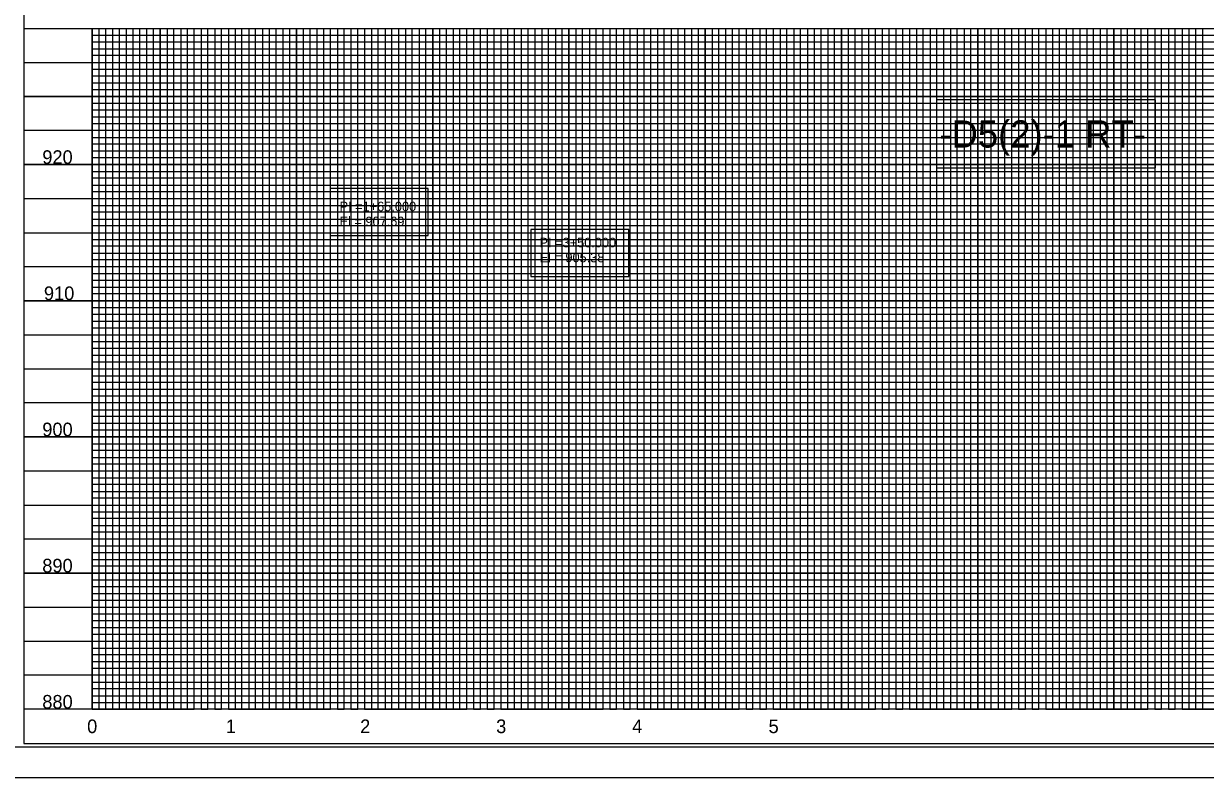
# Model space of a CAD drawing. Extents: x 1647943 to 1651624, y 802691 to 845761.
# Drawn here: x 1649029 to 1649896, y 802691 to 803245 of the extents above; entities that cross this region are included whole.
import ezdxf

# ---------------------------------------------------------------- set-up
doc = ezdxf.new("R2010")
doc.units = 0
for name, color, linetype in [('Exist Vertical Profile Horizontal Axis Label Major', 7, 'Continuous'), ('Exist Vertical Profile Vertical Axis Label', 7, 'Continuous'), ('Prop Grid Mask', 7, 'Continuous'), ('Prop VPI Ditch Grade Left Label', 7, 'Continuous'), ('Sheet Cutting Line CELL', 7, 'Continuous'), ('Sheet DOT Grid CELL', 7, 'Continuous'), ('Sheet Layout Profile Border Port 2', 7, 'Continuous'), ('Sheet Plot Border Inside CELL', 7, 'Continuous'), ('Sheet Plot Border Outside CELL', 7, 'Continuous'), ('Sheet Profile CELL', 7, 'Continuous'), ('Sheet Profile Grid Major CELL', 7, 'Continuous'), ('Sheet Profile Grid Middle CELL', 7, 'Continuous'), ('Sheet Profile Grid Minor CELL', 7, 'Continuous')]:
    doc.layers.add(name, color=color, linetype=linetype)

msp = doc.modelspace()

# ---------------------------------------------------------------- linework, layer by layer
at = {"layer": 'Prop Grid Mask'}
for points in [[(1649699.16, 803188.52), (1649699.16, 803138.61), (1649859.68, 803138.61), (1649859.68, 803188.52)], [(1649253.92, 803123.44), (1649253.92, 803089.03), (1649325.9, 803089.03), (1649325.9, 803123.44)], [(1649401.34, 803093.34), (1649401.34, 803058.94), (1649473.32, 803058.94), (1649473.32, 803093.34)]]:
    msp.add_lwpolyline(points, close=True, dxfattribs=at)
at = {"layer": 'Sheet Cutting Line CELL'}
msp.add_line((1648862.28, 802691.02), (1650546.28, 802691.02), dxfattribs=at)
at = {"layer": 'Sheet DOT Grid CELL'}
for p, q in [((1649029.28, 803241.02), (1650529.17, 803241.02)), ((1649079.28, 803241.02), (1649079.28, 802741.02)), ((1649129.28, 803241.02), (1649129.28, 802741.02)), ((1649179.28, 803241.02), (1649179.28, 802741.02)), ((1649229.28, 803241.02), (1649229.28, 802741.02)), ((1649279.28, 803241.02), (1649279.28, 802741.02)), ((1649329.28, 803241.02), (1649329.28, 802741.02)), ((1649379.28, 803241.02), (1649379.28, 802741.02)), ((1649429.28, 803241.02), (1649429.28, 802741.02)), ((1649479.28, 803241.02), (1649479.28, 802741.02)), ((1649529.28, 803241.02), (1649529.28, 802741.02)), ((1649579.28, 803241.02), (1649579.28, 802741.02)), ((1649629.28, 803241.02), (1649629.28, 802741.02)), ((1649679.28, 803241.02), (1649679.28, 802741.02)), ((1649729.28, 803241.02), (1649729.28, 802741.02)), ((1649779.28, 803241.02), (1649779.28, 802741.02)), ((1649829.28, 803241.02), (1649829.28, 802741.02)), ((1649879.28, 803241.02), (1649879.28, 802741.02)), ((1649029.28, 803191.02), (1650529.17, 803191.02)), ((1649029.28, 803141.02), (1650529.17, 803141.02)), ((1649029.28, 803091.02), (1650529.17, 803091.02)), ((1649029.28, 803041.02), (1650529.17, 803041.02)), ((1649029.28, 802991.02), (1650529.17, 802991.02)), ((1649029.28, 802941.02), (1650529.17, 802941.02)), ((1649029.28, 802891.02), (1650529.17, 802891.02)), ((1649029.28, 802841.02), (1650529.17, 802841.02)), ((1649029.28, 802791.02), (1650529.17, 802791.02))]:
    msp.add_line(p, q, dxfattribs=at)
at = {"layer": 'Sheet Layout Profile Border Port 2'}
msp.add_lwpolyline([(1649079.28, 803241.02), (1650479.28, 803241.02), (1650479.28, 802741.02), (1649079.28, 802741.02)], close=True, dxfattribs=at)
at = {"layer": 'Sheet Plot Border Inside CELL'}
msp.add_lwpolyline([(1648875.28, 802713.47), (1650541.78, 802713.47), (1650541.78, 803768.57), (1648875.28, 803768.57)], close=True, dxfattribs=at)
at = {"layer": 'Sheet Plot Border Outside CELL'}
msp.add_lwpolyline([(1648862.28, 802691.02), (1650546.28, 802691.02), (1650546.28, 803791.02), (1648862.28, 803791.02)], close=True, dxfattribs=at)
at = {"layer": 'Sheet Profile CELL'}
for p, q in [((1649029.28, 803241.02), (1650529.28, 803241.02)), ((1650529.28, 802741.02), (1649029.28, 802741.02)), ((1649029.28, 802716.02), (1650529.28, 802716.02)), ((1649029.28, 802716.02), (1649029.28, 802716.02)), ((1649029.28, 802716.02), (1649029.28, 802716.02)), ((1649029.28, 802716.02), (1649029.28, 802716.02)), ((1649029.28, 802716.02), (1649029.28, 802716.02)), ((1649029.28, 802716.02), (1649029.28, 802716.02)), ((1649029.28, 802716.02), (1649029.28, 802716.02)), ((1649029.28, 802716.02), (1649029.28, 802716.02))]:
    msp.add_line(p, q, dxfattribs=at)
msp.add_lwpolyline([(1650529.28, 803766.02), (1649029.28, 803766.02), (1649029.28, 802716.02), (1650529.28, 802716.02)], close=True, dxfattribs=at)
msp.add_lwpolyline([(1649066.78, 802716.02), (1649066.78, 802716.02)], dxfattribs=at)
at = {"layer": 'Sheet Profile Grid Major CELL'}
for p, q in [((1649529.28, 803241.02), (1649579.28, 803241.02)), ((1649629.28, 803241.02), (1649679.28, 803241.02)), ((1649729.28, 803241.02), (1649779.28, 803241.02)), ((1649829.28, 803241.02), (1649879.28, 803241.02)), ((1649029.28, 802741.02), (1649029.28, 802741.02))]:
    msp.add_line(p, q, dxfattribs=at)
for points in [[(1649079.28, 803241.02), (1649079.28, 802741.02), (1649129.28, 802741.02), (1649129.28, 803241.02), (1649179.28, 803241.02), (1649179.28, 802741.02), (1649229.28, 802741.02), (1649229.28, 803241.02), (1649279.28, 803241.02), (1649279.28, 802741.02), (1649329.28, 802741.02), (1649329.28, 803241.02), (1649379.28, 803241.02), (1649379.28, 802741.02), (1649429.28, 802741.02), (1649429.28, 803241.02), (1649479.28, 803241.02), (1649479.28, 802741.02), (1649529.28, 802741.02), (1649529.28, 803241.02), (1649579.28, 803241.02), (1649579.28, 802741.02), (1649629.28, 802741.02), (1649629.28, 803241.02), (1649679.28, 803241.02), (1649679.28, 802741.02), (1649729.28, 802741.02), (1649729.28, 803241.02), (1649779.28, 803241.02), (1649779.28, 802741.02), (1649829.28, 802741.02), (1649829.28, 803241.02), (1649879.28, 803241.02), (1649879.28, 802741.02), (1649929.28, 802741.02)], [(1650529.28, 803191.02), (1649029.28, 803191.02)], [(1650529.28, 803141.02), (1649029.28, 803141.02), (1649029.28, 803091.02), (1650529.28, 803091.02)], [(1650529.28, 803041.02), (1649029.28, 803041.02), (1649029.28, 802991.02), (1650529.28, 802991.02)], [(1650529.28, 802941.02), (1649029.28, 802941.02), (1649029.28, 802891.02), (1650529.28, 802891.02)], [(1650529.28, 802841.02), (1649029.28, 802841.02), (1649029.28, 802841.02), (1649029.28, 802791.02), (1650529.28, 802791.02)], [(1650529.28, 802741.02), (1649029.28, 802741.02)]]:
    msp.add_lwpolyline(points, dxfattribs=at)
at = {"layer": 'Sheet Profile Grid Middle CELL'}
for points in [[(1649054.28, 803241.02), (1649104.28, 803241.02), (1649104.28, 802741.02), (1649154.28, 802741.02), (1649154.28, 803241.02), (1649204.28, 803241.02), (1649204.28, 802741.02), (1649254.28, 802741.02), (1649254.28, 803241.02), (1649304.28, 803241.02), (1649304.28, 802741.02), (1649354.28, 802741.02), (1649354.28, 803241.02), (1649404.28, 803241.02), (1649404.28, 802741.02), (1649454.28, 802741.02), (1649454.28, 803241.02), (1649504.28, 803241.02), (1649504.28, 802741.02), (1649554.28, 802741.02), (1649554.28, 803241.02), (1649604.28, 803241.02), (1649604.28, 802741.02), (1649654.28, 802741.02), (1649654.28, 802741.02), (1649654.28, 803241.02), (1649704.28, 803241.02), (1649704.28, 802741.02), (1649754.28, 802741.02), (1649754.28, 803241.02), (1649804.28, 803241.02), (1649804.28, 802741.02), (1649854.28, 802741.02), (1649854.28, 803241.02), (1649904.28, 803241.02)], [(1649029.28, 803216.02), (1650529.28, 803216.02)], [(1650529.28, 803166.02), (1649029.28, 803166.02), (1649029.28, 803116.02), (1650529.28, 803116.02)], [(1650529.28, 803066.02), (1649029.28, 803066.02), (1649029.28, 803016.02), (1650529.28, 803016.02)], [(1650529.28, 802966.02), (1649029.28, 802966.02), (1649029.28, 802916.02), (1650529.28, 802916.02)], [(1650529.28, 802866.02), (1649029.28, 802866.02), (1649029.28, 802816.02), (1650529.28, 802816.02)], [(1650529.28, 802766.02), (1649029.28, 802766.02)]]:
    msp.add_lwpolyline(points, dxfattribs=at)
at = {"layer": 'Sheet Profile Grid Minor CELL'}
for p, q in [((1649079.28, 803236.02), (1650479.28, 803236.02)), ((1650479.28, 803231.02), (1649079.28, 803231.02)), ((1649079.28, 803226.02), (1650479.28, 803226.02)), ((1650479.28, 803221.02), (1649079.28, 803221.02)), ((1649079.28, 803211.02), (1650479.28, 803211.02)), ((1650479.28, 803206.02), (1649079.28, 803206.02)), ((1649079.28, 803201.02), (1650479.28, 803201.02)), ((1650479.28, 803196.02), (1649079.28, 803196.02)), ((1649079.28, 803186.02), (1650479.28, 803186.02)), ((1650479.28, 803181.02), (1649079.28, 803181.02)), ((1649079.28, 803176.02), (1650479.28, 803176.02)), ((1650479.28, 803171.02), (1649079.28, 803171.02)), ((1649079.28, 803161.02), (1650479.28, 803161.02)), ((1650479.28, 803156.02), (1649079.28, 803156.02)), ((1649079.28, 803151.02), (1650479.28, 803151.02)), ((1650479.28, 803146.02), (1649079.28, 803146.02)), ((1649079.28, 803136.02), (1650479.28, 803136.02)), ((1650479.28, 803131.02), (1649079.28, 803131.02)), ((1649079.28, 803126.02), (1650479.28, 803126.02)), ((1650479.28, 803121.02), (1649079.28, 803121.02)), ((1649079.28, 803111.02), (1650479.28, 803111.02)), ((1650479.28, 803106.02), (1649079.28, 803106.02)), ((1649079.28, 803101.02), (1650479.28, 803101.02)), ((1650479.28, 803096.02), (1649079.28, 803096.02)), ((1649079.28, 803086.02), (1650479.28, 803086.02)), ((1650479.28, 803081.02), (1649079.28, 803081.02)), ((1649079.28, 803076.02), (1650479.28, 803076.02)), ((1650479.28, 803071.02), (1649079.28, 803071.02)), ((1649079.28, 803061.02), (1650479.28, 803061.02)), ((1650479.28, 803056.02), (1649079.28, 803056.02)), ((1649079.28, 803051.02), (1650479.28, 803051.02)), ((1650479.28, 803046.02), (1649079.28, 803046.17)), ((1649079.28, 803036.02), (1650479.28, 803036.02)), ((1650479.28, 803031.02), (1649079.28, 803031.02)), ((1649079.28, 803026.02), (1650479.28, 803026.02)), ((1650479.28, 803021.02), (1649079.28, 803021.02)), ((1649079.28, 803011.02), (1650479.28, 803011.02)), ((1650479.28, 803006.02), (1649079.28, 803006.02)), ((1649079.28, 803001.02), (1650479.28, 803001.02)), ((1650479.28, 802996.02), (1649079.28, 802996.02)), ((1649079.28, 802986.02), (1650479.28, 802986.02)), ((1650479.28, 802981.02), (1649079.28, 802981.02)), ((1649079.28, 802976.02), (1650479.28, 802976.02)), ((1650479.28, 802971.02), (1649079.28, 802971.02)), ((1649079.28, 802961.02), (1650479.28, 802961.02)), ((1650479.28, 802956.02), (1649079.28, 802956.02)), ((1649079.28, 802951.02), (1650479.28, 802951.02)), ((1650479.28, 802946.02), (1649079.28, 802946.02)), ((1649079.28, 802936.02), (1650479.28, 802936.02)), ((1650479.28, 802931.02), (1649079.28, 802931.02)), ((1649079.28, 802926.02), (1650479.28, 802926.02)), ((1650479.28, 802921.02), (1649079.28, 802921.02)), ((1649079.28, 802911.02), (1650479.28, 802911.02)), ((1650479.28, 802906.02), (1649079.28, 802906.02)), ((1649079.28, 802901.02), (1650479.28, 802901.02)), ((1650479.28, 802896.02), (1649079.28, 802896.02)), ((1649079.28, 802886.02), (1650479.28, 802886.02)), ((1650479.28, 802881.02), (1649079.28, 802881.02)), ((1649079.28, 802876.02), (1650479.28, 802876.02)), ((1650479.28, 802871.02), (1649079.28, 802871.02)), ((1649079.28, 802861.02), (1650479.28, 802861.02)), ((1650479.28, 802856.02), (1649079.28, 802856.02)), ((1649079.28, 802851.02), (1650479.28, 802851.02)), ((1650479.28, 802846.02), (1649079.28, 802846.02)), ((1649079.28, 802836.02), (1650479.28, 802836.02)), ((1650479.28, 802831.02), (1649079.28, 802831.02)), ((1649079.28, 802826.02), (1650479.28, 802826.02)), ((1650479.28, 802821.02), (1649079.28, 802821.02)), ((1649079.28, 802811.02), (1650479.28, 802811.02)), ((1650479.28, 802806.02), (1649079.28, 802806.02)), ((1649079.28, 802801.02), (1650479.28, 802801.02)), ((1650479.28, 802796.02), (1649079.28, 802796.02)), ((1649079.28, 802786.02), (1650479.28, 802786.02)), ((1650479.28, 802781.02), (1649079.28, 802781.02)), ((1649079.28, 802776.02), (1650479.28, 802776.02)), ((1650479.28, 802771.02), (1649079.28, 802771.02)), ((1649079.28, 802761.02), (1650479.28, 802761.02)), ((1650479.28, 802756.02), (1649079.28, 802756.02)), ((1649079.28, 802751.02), (1650479.28, 802751.02)), ((1649079.28, 802746.02), (1650479.28, 802746.02))]:
    msp.add_line(p, q, dxfattribs=at)
for points in [[(1649079.28, 803241.02), (1649084.28, 803241.02), (1649084.28, 802741.02), (1649089.28, 802741.02), (1649089.28, 803241.02), (1649094.28, 803241.02), (1649094.28, 802741.02), (1649099.28, 802741.02), (1649099.28, 803241.02), (1649109.28, 803241.02), (1649109.28, 802741.02), (1649114.28, 802741.02), (1649114.28, 803241.02), (1649119.28, 803241.02), (1649119.28, 802741.02), (1649124.28, 802741.02), (1649134.28, 802741.02), (1649139.28, 802741.02), (1649139.28, 803241.02), (1649144.28, 803241.02), (1649144.28, 802741.02), (1649149.28, 802741.02), (1649149.28, 803241.02), (1649159.28, 803241.02), (1649159.28, 802741.02), (1649164.28, 802741.02), (1649164.28, 803241.02), (1649169.28, 803241.02), (1649169.28, 802741.02), (1649174.28, 802741.02), (1649174.28, 803241.02), (1649184.28, 803241.02), (1649184.28, 802741.02), (1649189.28, 802741.02), (1649189.28, 803241.02), (1649194.28, 803241.02), (1649194.28, 802741.02), (1649199.28, 802741.02), (1649199.28, 803241.02), (1649209.28, 803241.02), (1649209.28, 802741.02), (1649214.28, 802741.02), (1649214.28, 803241.02), (1649219.28, 803241.02), (1649219.28, 802741.02), (1649224.28, 802741.02), (1649224.28, 803241.02), (1649234.28, 803241.02), (1649234.28, 802741.02), (1649239.28, 802741.02), (1649239.28, 803241.02), (1649244.28, 803241.02), (1649244.28, 802741.02), (1649249.28, 802741.02), (1649249.28, 803241.02), (1649259.28, 803241.02), (1649259.28, 802741.02), (1649264.28, 802741.02), (1649264.28, 803241.02), (1649269.28, 803241.02), (1649269.28, 802741.02), (1649274.28, 802741.02), (1649274.28, 803241.02), (1649284.28, 803241.02), (1649284.28, 802741.02), (1649289.28, 802741.02), (1649289.28, 803241.02), (1649294.28, 803241.02), (1649294.28, 802741.02)], [(1649124.28, 802741.02), (1649124.28, 803241.02), (1649134.28, 803241.02), (1649134.28, 802741.02)], [(1649294.28, 802741.02), (1649299.28, 802741.02), (1649299.28, 803241.02), (1649309.28, 803241.02), (1649309.28, 802741.02), (1649314.28, 802741.02), (1649314.28, 803241.02), (1649319.28, 803241.02), (1649319.28, 802741.02), (1649324.28, 802741.02), (1649324.28, 803241.02), (1649334.28, 803241.02), (1649334.28, 802741.02), (1649339.28, 802741.02), (1649339.28, 803241.02), (1649344.28, 803241.02), (1649344.28, 802741.02), (1649349.28, 802741.02), (1649349.28, 803241.02), (1649359.28, 803241.02), (1649359.28, 802741.02), (1649364.28, 802741.02), (1649364.28, 803241.02), (1649369.28, 803241.02), (1649369.28, 802741.02), (1649374.28, 802741.02), (1649374.28, 803241.02), (1649384.28, 803241.02), (1649384.28, 802741.02), (1649389.28, 802741.02), (1649389.28, 803241.02), (1649394.28, 803241.02), (1649394.28, 802741.02), (1649399.28, 802741.02), (1649399.28, 803241.02), (1649409.28, 803241.02), (1649409.28, 802741.02), (1649414.28, 802741.02), (1649414.28, 803241.02), (1649419.28, 803241.02), (1649419.28, 802741.02), (1649424.28, 802741.02), (1649424.28, 803241.02), (1649434.28, 803241.02), (1649434.28, 802741.02), (1649439.28, 802741.02), (1649439.28, 803241.02), (1649444.28, 803241.02), (1649444.28, 802741.02), (1649449.28, 802741.02), (1649449.28, 803241.02), (1649459.28, 803241.02), (1649459.28, 802741.02), (1649464.28, 802741.02), (1649464.28, 803241.02), (1649469.28, 803241.02), (1649469.28, 802741.02), (1649474.28, 802741.02), (1649474.28, 803241.02), (1649484.28, 803241.02), (1649484.28, 802741.02), (1649489.28, 802741.02), (1649489.28, 803241.02), (1649494.28, 803241.02), (1649494.28, 802741.02), (1649499.28, 802741.02), (1649499.28, 803241.02), (1649509.28, 803241.02), (1649509.28, 802741.02), (1649514.28, 802741.02), (1649514.28, 803241.02), (1649519.28, 803241.02), (1649519.28, 802741.02), (1649524.28, 802741.02), (1649524.28, 803241.02), (1649534.28, 803241.02), (1649534.28, 802741.02), (1649539.28, 802741.02), (1649539.28, 803241.02), (1649544.28, 803241.02), (1649544.28, 802741.02), (1649549.28, 802741.02), (1649549.28, 803241.02), (1649559.28, 803241.02), (1649559.28, 802741.02), (1649564.28, 802741.02), (1649564.28, 803241.02), (1649569.28, 803241.02), (1649569.28, 802741.02), (1649574.28, 802741.02), (1649574.28, 803241.02), (1649584.28, 803241.02), (1649584.28, 802741.02), (1649589.28, 802741.02), (1649589.28, 803241.02), (1649594.28, 803241.02), (1649594.28, 802741.02), (1649599.28, 802741.02), (1649599.28, 803241.02), (1649609.28, 803241.02)], [(1649609.28, 803241.02), (1649609.28, 802741.02), (1649614.28, 802741.02), (1649614.28, 803241.02), (1649619.28, 803241.02), (1649619.28, 802741.02), (1649624.28, 802741.02), (1649624.28, 803241.02), (1649634.28, 803241.02), (1649634.28, 802741.02), (1649639.28, 802741.02), (1649639.28, 803241.02), (1649644.28, 803241.02), (1649644.28, 802741.02), (1649649.28, 802741.02), (1649649.28, 803241.02), (1649659.28, 803241.02), (1649659.28, 802741.02), (1649664.28, 802741.02), (1649664.28, 803241.02), (1649669.28, 803241.02), (1649669.28, 802741.02), (1649674.28, 802741.02), (1649674.28, 803241.02), (1649684.28, 803241.02), (1649684.28, 802741.02), (1649689.28, 802741.02), (1649689.28, 803241.02), (1649694.28, 803241.02), (1649694.28, 802741.02), (1649699.28, 802741.02), (1649699.28, 803241.02), (1649709.28, 803241.02), (1649709.28, 802741.02), (1649714.28, 802741.02), (1649714.28, 803241.02), (1649719.28, 803241.02), (1649719.28, 802741.02), (1649724.28, 802741.02), (1649724.28, 803241.02), (1649734.28, 803241.02), (1649734.28, 802741.02), (1649734.28, 802741.02), (1649739.28, 802741.02), (1649739.28, 803241.02), (1649744.28, 803241.02), (1649744.28, 802741.02), (1649749.28, 802741.02), (1649749.28, 803241.02), (1649759.28, 803241.02), (1649759.28, 802741.02), (1649764.28, 802741.02), (1649764.28, 803241.02), (1649769.28, 803241.02), (1649769.28, 802741.02), (1649774.28, 802741.02), (1649774.28, 803241.02), (1649784.28, 803241.02), (1649784.28, 802741.02), (1649789.28, 802741.02), (1649789.28, 803241.02), (1649794.28, 803241.02), (1649794.28, 802741.02), (1649799.28, 802741.02), (1649799.28, 803241.02), (1649809.28, 803241.02), (1649809.28, 802741.02), (1649814.28, 802741.02), (1649814.28, 803241.02), (1649819.28, 803241.02), (1649819.28, 802741.02), (1649824.28, 802741.02), (1649824.28, 803241.02), (1649834.28, 803241.02), (1649834.28, 802741.02), (1649839.28, 802741.02), (1649839.28, 803241.02), (1649844.28, 803241.02), (1649844.28, 802741.02), (1649849.28, 802741.02), (1649849.28, 803241.02), (1649859.28, 803241.02), (1649859.28, 802741.02), (1649864.28, 802741.02), (1649864.28, 803241.02), (1649869.28, 803241.02), (1649869.28, 802741.02), (1649874.28, 802741.02), (1649874.28, 803241.02), (1649884.28, 803241.02), (1649884.28, 802741.02), (1649888.98, 802741.57), (1649889.28, 802741.02), (1649889.28, 803241.02), (1649894.28, 803241.02), (1649894.28, 802741.02), (1649899.28, 802741.02)]]:
    msp.add_lwpolyline(points, dxfattribs=at)

# ---------------------------------------------------------------- texts
at = {"layer": 'Exist Vertical Profile Horizontal Axis Label Major'}
for s, height, p in [('-D5(2)-1 RT-', 20, (1649701.18, 803153.52)), ('0', 10, (1649075.62, 802723.52)), ('1', 10, (1649177.46, 802723.52)), ('2', 10, (1649276.01, 802723.52)), ('3', 10, (1649375.85, 802723.52)), ('4', 10, (1649475.69, 802723.52)), ('5', 10, (1649575.78, 802723.52))]:
    msp.add_text(s, height=height, dxfattribs=at).set_placement(p)
at = {"layer": 'Exist Vertical Profile Vertical Axis Label'}
for s, p in [('920', (1649042.71, 803141.52)), ('910', (1649043.91, 803041.52)), ('900', (1649042.71, 802941.52)), ('890', (1649042.71, 802841.52)), ('880', (1649042.71, 802741.52))]:
    msp.add_text(s, height=10, dxfattribs=at).set_placement(p)
at = {"layer": 'Prop VPI Ditch Grade Left Label'}
for s, p in [('PI =1+65.000', (1649260.91, 803106.78)), ('El = 907.69', (1649260.91, 803095.78)), ('PI =3+50.000', (1649407.69, 803080.29)), ('El = 905.38', (1649407.69, 803069.29))]:
    msp.add_text(s, height=7, dxfattribs=at).set_placement(p)

doc.saveas('drawing.dxf')
